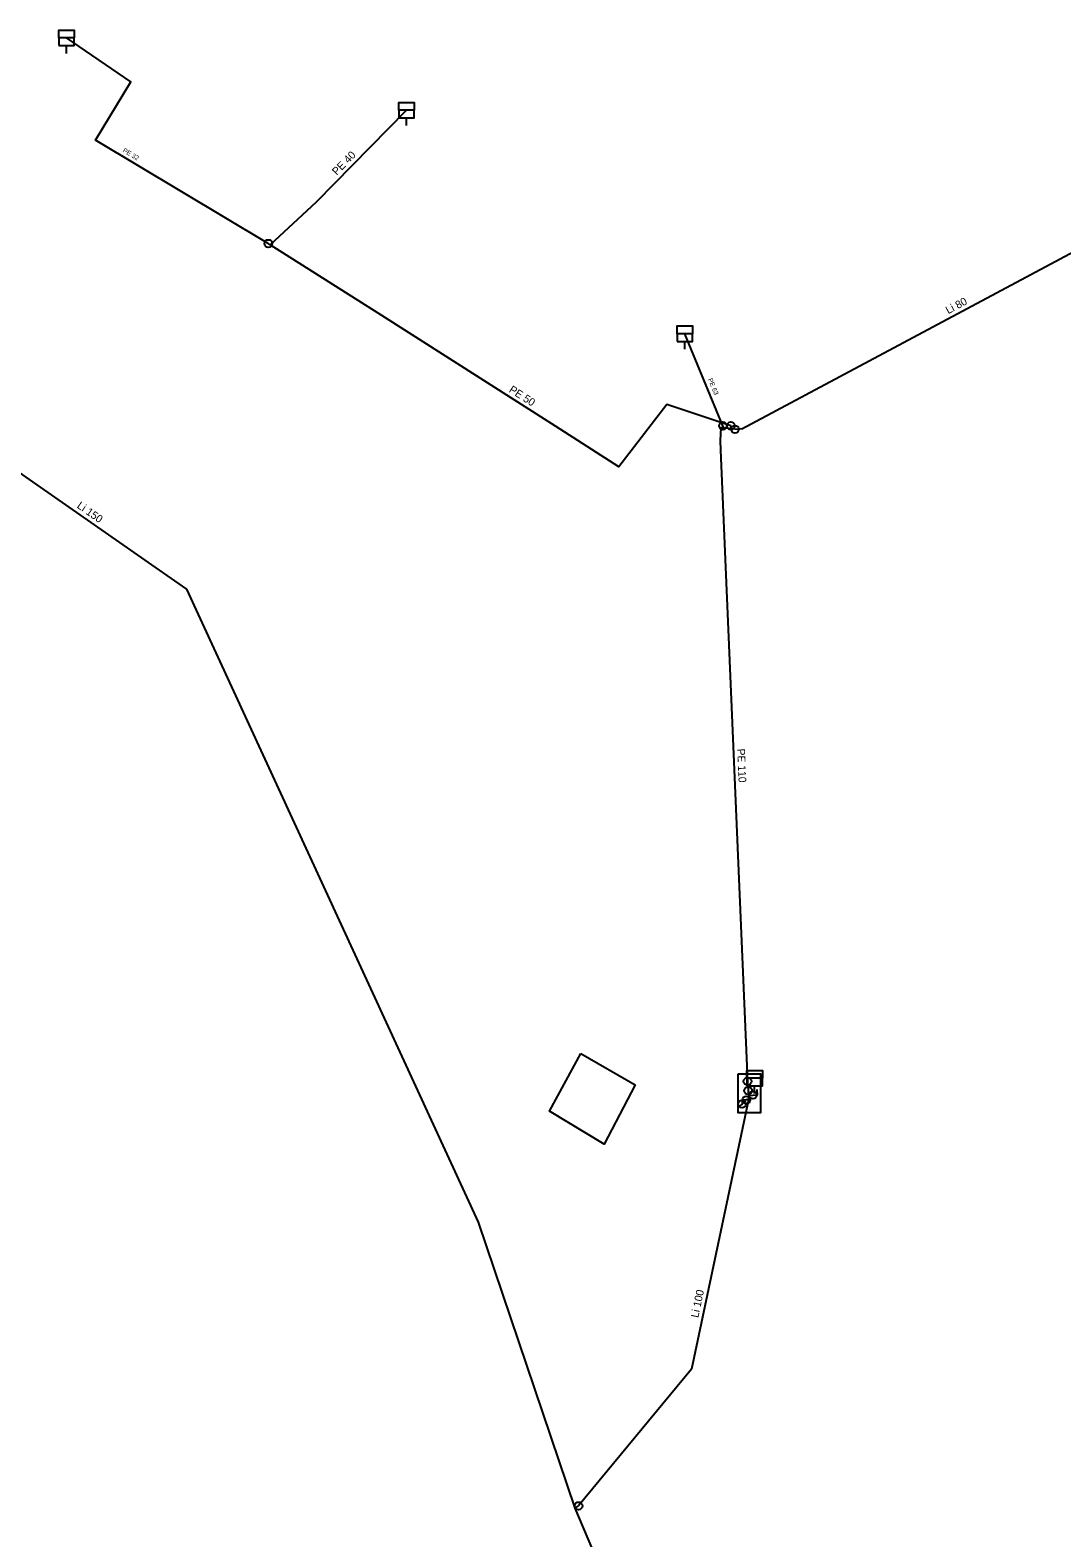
# Model space of a CAD drawing. Extents: x -770258 to -769930, y -1182247 to -1181932.
# Drawn here: x -770192.9 to -770126.1, y -1182175.3 to -1182077.8 of the extents above; entities that cross this region are included whole.
import ezdxf

# ---------------------------------------------------------------- set-up
doc = ezdxf.new("R2010")
doc.units = 0
for name, color, linetype in [('Objekty nadzemní', 7, 'Continuous'), ('Objekty podzemní', 7, 'Continuous'), ('Popis vodovodních řadů', 7, 'Continuous'), ('Vod přípojky-voda pitná', 7, 'Continuous'), ('Vodovodní řad', 7, 'Continuous'), ('Vodovodní šachty', 7, 'Continuous'), ('Vodovodní šoupata', 7, 'Continuous')]:
    doc.layers.add(name, color=color, linetype=linetype)

msp = doc.modelspace()

# ---------------------------------------------------------------- linework, layer by layer
at = {"layer": 'Objekty nadzemní'}
msp.add_lwpolyline([(-770157.26, -1182144), (-770153.73, -1182146.04), (-770155.75, -1182149.86), (-770159.27, -1182147.73), (-770157.26, -1182144)], dxfattribs=at)
at = {"layer": 'Objekty podzemní'}
msp.add_lwpolyline([(-770147.1, -1182145.33), (-770147.1, -1182147.83), (-770145.6, -1182147.83), (-770145.6, -1182145.33), (-770147.1, -1182145.33)], dxfattribs=at)
at = {"layer": 'Vod přípojky-voda pitná'}
for points in [[(-770177.34, -1182091.7), (-770177.47, -1182091.62), (-770188.64, -1182084.94), (-770186.36, -1182081.16), (-770190.52, -1182078.32)], [(-770148, -1182103.55), (-770148.06, -1182103.41), (-770150.53, -1182097.45)], [(-770146.4, -1182147.01), (-770146.55, -1182147.01), (-770146.82, -1182147.02), (-770146.82, -1182147.12), (-770146.82, -1182147.27), (-770147, -1182147.41)]]:
    msp.add_lwpolyline(points, dxfattribs=at)
at = {"layer": 'Vodovodní řad'}
for points in [[(-770177.34, -1182091.7), (-770174.35, -1182088.93), (-770168.53, -1182082.99)], [(-770146.83, -1182103.61), (-770119.91, -1182089.22)], [(-770147.55, -1182103.41), (-770151.69, -1182102.04), (-770154.8, -1182106.06), (-770158.9, -1182103.43), (-770170.36, -1182096.12), (-770177.34, -1182091.7)], [(-770182.73, -1182113.98), (-770184.5, -1182112.74), (-770197.35, -1182103.79)], [(-770147.48, -1182103.6), (-770148, -1182103.55), (-770148.2, -1182103.53), (-770148.23, -1182104.35), (-770148.21, -1182104.98), (-770146.47, -1182145.81)], [(-770147.48, -1182103.6), (-770147.55, -1182103.41)], [(-770147.28, -1182103.63), (-770147.48, -1182103.6)], [(-770146.83, -1182103.61), (-770147.09, -1182103.65), (-770147.28, -1182103.63)], [(-770127.336, -1182246.608), (-770134.11, -1182229.88), (-770138.64, -1182218.16), (-770157.61, -1182173.4), (-770163.87, -1182154.91), (-770182.73, -1182113.98)], [(-770146.47, -1182145.81), (-770146.45, -1182146.11)], [(-770146.41, -1182146.71), (-770146.4, -1182147.01), (-770150.1, -1182164.42), (-770157.4, -1182173.26)], [(-770146.45, -1182146.11), (-770146.43, -1182146.41)], [(-770146.43, -1182146.41), (-770146.41, -1182146.71)], [(-770146.41, -1182146.71), (-770146.12, -1182146.69)], [(-770146.12, -1182146.69), (-770145.82, -1182146.67), (-770145.85, -1182146.33)], [(-770157.61, -1182173.4), (-770157.4, -1182173.26)]]:
    msp.add_lwpolyline(points, dxfattribs=at)
at = {"layer": 'Vodovodní šachty'}
for p, q in [((-770190.52, -1182079.32), (-770190.52, -1182078.82)), ((-770168.53, -1182083.99), (-770168.53, -1182083.49)), ((-770150.53, -1182098.45), (-770150.53, -1182097.95)), ((-770146.01, -1182146.6), (-770146.01, -1182146.1))]:
    msp.add_line(p, q, dxfattribs=at)
for points in [[(-770191.02, -1182078.32), (-770191.02, -1182077.82), (-770190.02, -1182077.82), (-770190.02, -1182078.32)], [(-770169.03, -1182082.99), (-770169.03, -1182082.49), (-770168.03, -1182082.49), (-770168.03, -1182082.99)], [(-770151.03, -1182097.45), (-770151.03, -1182096.95), (-770150.03, -1182096.95), (-770150.03, -1182097.45)], [(-770146.51, -1182145.6), (-770146.51, -1182145.1), (-770145.51, -1182145.1), (-770145.51, -1182145.6)]]:
    msp.add_lwpolyline(points, dxfattribs=at)
for points in [[(-770191.02, -1182078.82), (-770190.02, -1182078.82), (-770190.02, -1182078.32), (-770191.02, -1182078.32)], [(-770169.03, -1182083.49), (-770168.03, -1182083.49), (-770168.03, -1182082.99), (-770169.03, -1182082.99)], [(-770151.03, -1182097.95), (-770150.03, -1182097.95), (-770150.03, -1182097.45), (-770151.03, -1182097.45)], [(-770146.51, -1182146.1), (-770145.51, -1182146.1), (-770145.51, -1182145.6), (-770146.51, -1182145.6)]]:
    msp.add_lwpolyline(points, close=True, dxfattribs=at)
at = {"layer": 'Vodovodní šoupata'}
for centre in [(-770177.47, -1182091.62), (-770148.06, -1182103.41), (-770147.55, -1182103.41), (-770147.28, -1182103.63), (-770146.47, -1182145.81), (-770146.55, -1182147.01), (-770146.43, -1182146.41), (-770146.12, -1182146.69), (-770146.82, -1182147.27), (-770157.4, -1182173.26)]:
    msp.add_circle(centre, 0.25, dxfattribs=at)

# ---------------------------------------------------------------- texts
at = {"layer": 'Popis vodovodních řadů'}
for s, height, rotation, p in [('PE 32', 0.3, 329.11929, (-770186.917, -1182085.679)), ('PE 40', 0.5, 45.58463, (-770173.045, -1182087.241)), ('Li 80', 0.5, 28.12659, (-770133.488, -1182096.195)), ('PE 50', 0.5, 327.46738, (-770161.944, -1182101.192)), ('PE 63', 0.3, 292.51056, (-770149.035, -1182100.405)), ('Li 150', 0.5, 325.14286, (-770189.895, -1182108.677)), ('PE 110', 0.5, 272.44022, (-770147.137, -1182124.298)), ('Li 100', 0.5, 78.00192, (-770149.655, -1182161.123))]:
    msp.add_text(s, height=height, rotation=rotation, dxfattribs=at).set_placement(p)

doc.saveas('drawing.dxf')
